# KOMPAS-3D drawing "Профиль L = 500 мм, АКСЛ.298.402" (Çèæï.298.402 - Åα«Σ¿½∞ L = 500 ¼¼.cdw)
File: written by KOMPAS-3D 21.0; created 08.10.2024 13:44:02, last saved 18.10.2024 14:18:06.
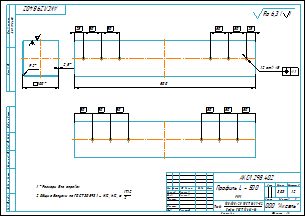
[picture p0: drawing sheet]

Sheet 1: A3, landscape

Document properties: Полное имя файла: C:\Users\Алексей Бочаров\YandexDisk\Соединения бруса\Соединения бруса\КВАТРО\АКСЛ.298.402 - Профиль L = 500 мм.cdw; Автор: Алексей Бочаров; Знак неуказанной шероховатости: 4; Параметр неуказанной шероховатости: Ra 6,3; Масса: 3.029613

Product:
- Part/product: Профиль L = 500 мм  | designation АКСЛ.298.402
    Масса: 3.029613
    Форматы листов документа: A3

Title block, sheet 1: Наименование: Профиль L = 500 / мм; designation: АКСЛ.298.402; Материал: Труба  100х100х2,5 ГОСТ 8639-82 Ст3сп ГОСТ 13663-86; Масса: 3,03; Количество листов документа: 1; organisation: ООО "Аксель"; Форматы листов документа: A3; stored path: C:\Users\Алексей Бочаров\Desktop\Соединения бруса\ТРИО\Профиль L = 300 мм (1) — копия.cdw; Разработал: Бочаров; Проверил: Захаров; Утвердил: Гелетей

Views: Вид 1, Справа, Проекционный вид 2, Проекционный вид 3
Referenced files in C:\Users\Алексей Бочаров\Desktop\Соединения бруса\КВАТРО\: Профиль L = 500 мм.m3d
Referenced files in C:\Users\Алексей Бочаров\YandexDisk\Соединения бруса\Соединения бруса\КВАТРО\: Профиль L = 500 мм.m3d
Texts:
  Ra 6,3
  Ra 6,3 ( )
  АКСЛ.298.400
  АКСЛ.298.402 Профиль L = 500 мм
Dimensions and other numbers on the sheet: 500; 12 отв.; 8; 25; 50; 100; 2; 2,5; 1:2; 1; 3,03

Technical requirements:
  *Размеры для справок.
  Общие допуски по ГОСТ 30893.1 - H12, h12,    IT12 2 .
